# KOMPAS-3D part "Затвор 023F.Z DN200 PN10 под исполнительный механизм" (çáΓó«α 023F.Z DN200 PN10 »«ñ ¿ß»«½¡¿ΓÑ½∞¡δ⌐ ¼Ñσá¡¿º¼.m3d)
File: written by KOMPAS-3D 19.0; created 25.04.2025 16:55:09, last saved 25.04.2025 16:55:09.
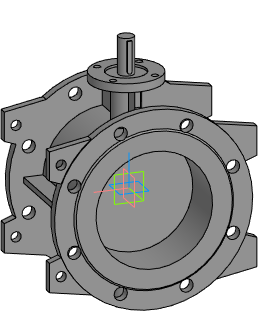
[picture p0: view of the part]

Document properties: Автор: Евгений; Полное имя файла: E:\Dendor Работа Сачек\3D для проекитирвщиков\1.7 Тип 023F.Z Затвор дисковый поворотный фланцевый с двумя эксцентриками\stp_Тип 023F.Z. Затвор под исполн. механизм\Затвор 023F.Z DN200 PN10 под исполнительный механизм.m3d

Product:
- Part/product: Затвор 023F.Z DN200 PN10 под исполнительный механизм

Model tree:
1. Операция без истории:1  (labels: Затвор 023F.Z DN200 PN10 под исполнительный механизм)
